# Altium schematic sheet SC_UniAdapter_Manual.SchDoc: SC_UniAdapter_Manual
size A4; Date: 2023.10.30; Revision: V1.0
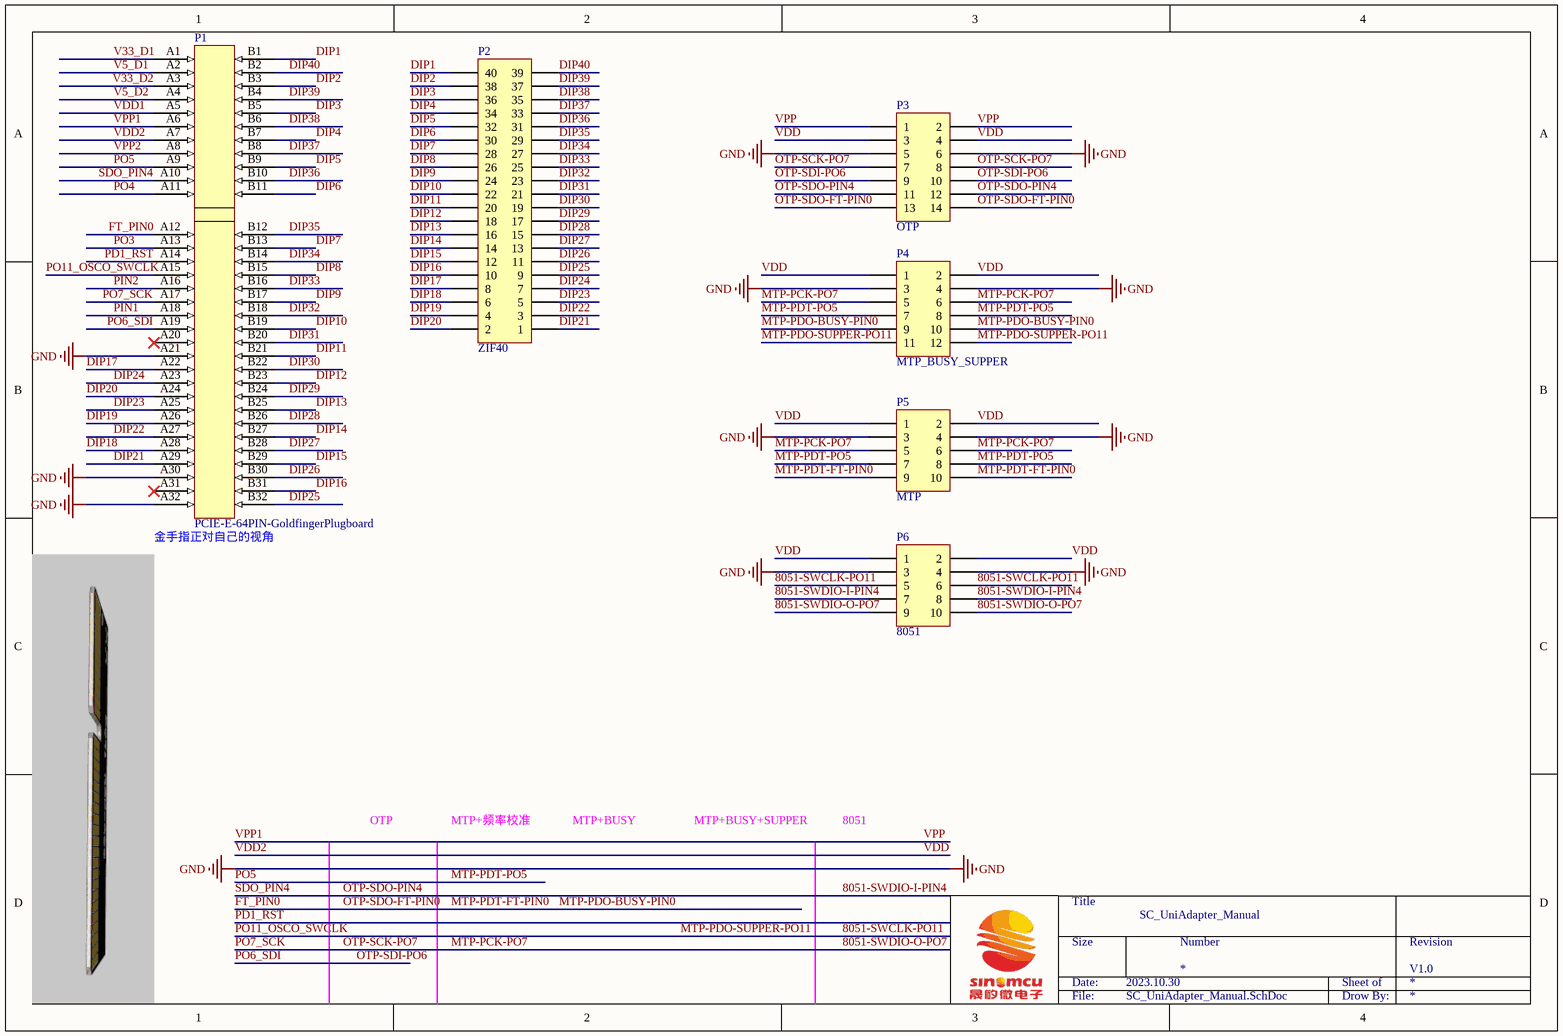
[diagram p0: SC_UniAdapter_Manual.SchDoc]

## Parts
P1  PCIE-E-64PIN-GoldfingerPlugboard  [PCIE-E-64-GoldfingerPlug]
P2  ZIF40  [HDR2X20]
P3  OTP  [HDR2X7H]
P4  MTP_BUSY_SUPPER  [HDR2X6H]
P5  MTP  [HDR2X5H]
P6  8051  [HDR2X5H]

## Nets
GND: P1.A21 P1.A30 P1.A32 P3.5 P3.6 P4.3 P4.4 P5.3 P5.4 P6.3 P6.4
8051-SWCLK-PO11: P1.A15 P4.11 P4.12 P6.5 P6.6  [also labelled MTP-PDO-SUPPER-PO11, PO11_OSCO_SWCLK]
8051-SWDIO-I-PIN4: P1.A10 P3.11 P3.12 P6.7 P6.8  [also labelled OTP-SDO-PIN4, SDO_PIN4]
8051-SWDIO-O-PO7: P1.A17 P3.7 P3.8 P4.5 P4.6 P5.5 P5.6 P6.9 P6.10  [also labelled MTP-PCK-PO7, OTP-SCK-PO7, PO7_SCK]
DIP1: P1.B1 P2.40
DIP2: P1.B3 P2.38
DIP3: P1.B5 P2.36
DIP4: P1.B7 P2.34
DIP5: P1.B9 P2.32
DIP6: P1.B11 P2.30
DIP7: P1.B13 P2.28
DIP8: P1.B15 P2.26
DIP9: P1.B17 P2.24
DIP10: P1.B19 P2.22
DIP11: P1.B21 P2.20
DIP12: P1.B23 P2.18
DIP13: P1.B25 P2.16
DIP14: P1.B27 P2.14
DIP15: P1.B29 P2.12
DIP16: P1.B31 P2.10
DIP17: P1.A22 P2.8
DIP18: P1.A28 P2.6
DIP19: P1.A26 P2.4
DIP20: P1.A24 P2.2
DIP21: P1.A29 P2.1
DIP22: P1.A27 P2.3
DIP23: P1.A25 P2.5
DIP24: P1.A23 P2.7
DIP25: P1.B32 P2.9
DIP26: P1.B30 P2.11
DIP27: P1.B28 P2.13
DIP28: P1.B26 P2.15
DIP29: P1.B24 P2.17
DIP30: P1.B22 P2.19
DIP31: P1.B20 P2.21
DIP32: P1.B18 P2.23
DIP33: P1.B16 P2.25
DIP34: P1.B14 P2.27
DIP35: P1.B12 P2.29
DIP36: P1.B10 P2.31
DIP37: P1.B8 P2.33
DIP38: P1.B6 P2.35
DIP39: P1.B4 P2.37
DIP40: P1.B2 P2.39
FT_PIN0: P1.A12 P3.13 P3.14 P4.9 P4.10 P5.9 P5.10  [also labelled MTP-PDO-BUSY-PIN0, MTP-PDT-FT-PIN0, OTP-SDO-FT-PIN0]
MTP-PDT-PO5: P1.A9 P4.7 P4.8 P5.7 P5.8  [also labelled PO5]
OTP-SDI-PO6: P1.A19 P3.9 P3.10  [also labelled PO6_SDI]
PD1_RST: P1.A14
PIN1: P1.A18
PIN2: P1.A16
PO3: P1.A13
PO4: P1.A11
V5_D1: P1.A2
V5_D2: P1.A4
V33_D1: P1.A1
V33_D2: P1.A3
VDD: P1.A7 P3.3 P3.4 P4.1 P4.2 P5.1 P5.2 P6.1 P6.2  [also labelled VDD2]
VDD1: P1.A5
VPP: P1.A6 P3.1 P3.2  [also labelled VPP1]
VPP2: P1.A8

Not connected (* = marked no-connect by the designer): P1 A20* A31*

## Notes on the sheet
- (near P1) 金手指正对自己的视角
- OTP
- MTP+频率校准
- MTP+BUSY
- MTP+BUSY+SUPPER
- 8051

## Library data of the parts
P1 = CMP-002-000020-2: PCIE-E 64脚 金手指插板
P2 = Header 20X2: Header, 20-Pin, Dual row
P3 = Header 7X2H: Header, 7-Pin, Dual row, Right Angle
P4 = Header 6X2H: Header, 6-Pin, Dual row, Right Angle
P5 P6 = Header 5X2H: Header, 5-Pin, Dual row, Right Angle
